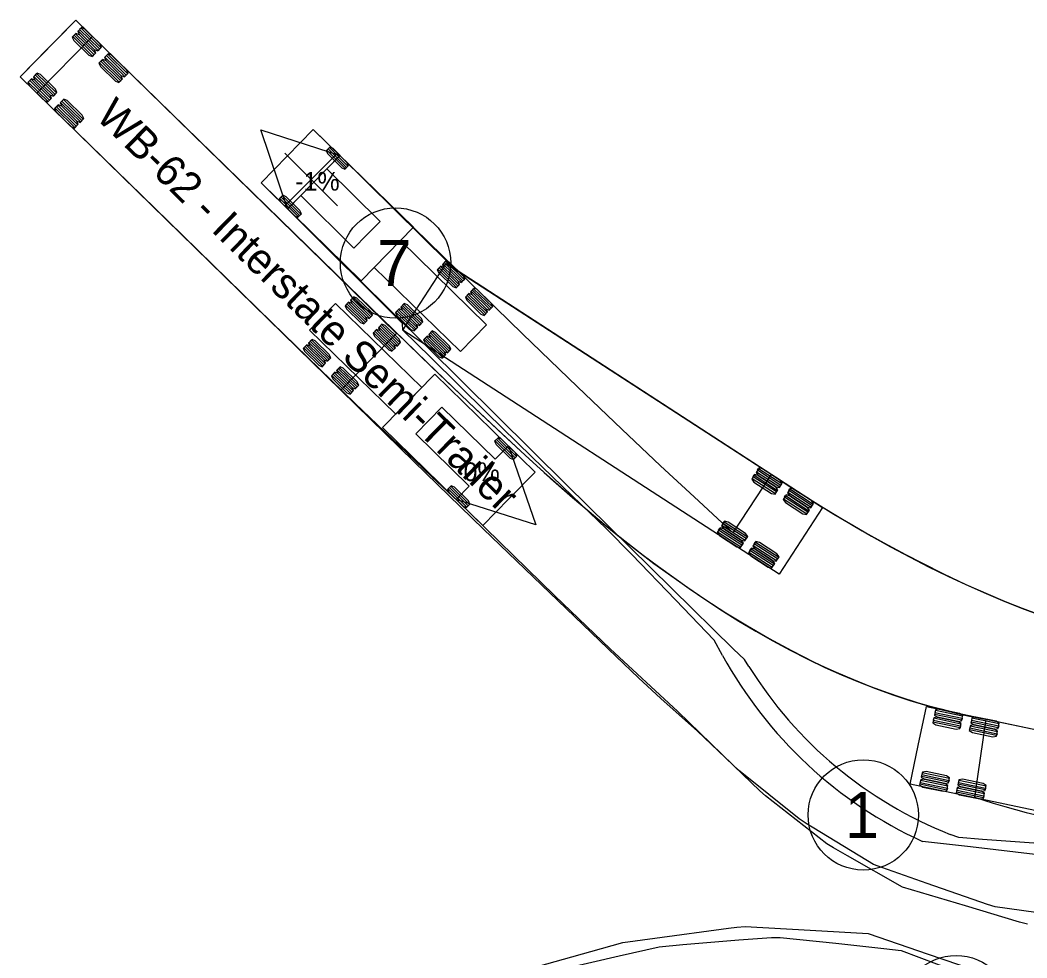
# Model space of a CAD drawing. Extents: x 1475900 to 1484331, y 375914 to 383395.
# Drawn here: x 1478966.1 to 1479073.9, y 379974.6 to 380075 of the extents above; entities that cross this region are included whole.
import ezdxf

# ---------------------------------------------------------------- set-up
doc = ezdxf.new("R2010")
doc.units = 0
doc.layers.add('0 (Construction)', color=7, linetype='Continuous')
doc.layers.add('Default', color=7, linetype='Continuous')

# ---------------------------------------------------------------- blocks, each defined once
blk = doc.blocks.new('ATRPTH')
at = {"layer": '0 (Construction)'}
blk.add_lwpolyline([(375813.922, 96513.365), (375814.277, 96513.729), (375815.731, 96512.309), (375816.086, 96512.672), (375816.829, 96510.525), (375814.666, 96511.219), (375815.021, 96511.582), (375813.567, 96513.002), (375813.922, 96513.365)], dxfattribs=at)
blk.add_circle((375825.735, 96502.636), 1.5, dxfattribs=at)
at = {"layer": 'Default'}
for points in [[(375804.321, 96524.255), (375811.738, 96517.015), (375813.875, 96514.943), (375815.01, 96513.855), (375815.898, 96513.017), (375816.541, 96512.422), (375817.056, 96511.954), (375817.581, 96511.49), (375818.11, 96511.033), (375818.515, 96510.692), (375818.921, 96510.358), (375819.336, 96510.029), (375819.752, 96509.704), (375820.165, 96509.395), (375820.58, 96509.093), (375821.005, 96508.796), (375821.429, 96508.508), (375821.999, 96508.136), (375822.586, 96507.777), (375823.179, 96507.434), (375823.781, 96507.109), (375824.081, 96506.954), (375824.384, 96506.805), (375824.689, 96506.659), (375824.999, 96506.519), (375825.467, 96506.316), (375825.936, 96506.128), (375826.408, 96505.954), (375826.725, 96505.847), (375827.202, 96505.695), (375827.522, 96505.603), (375827.843, 96505.518), (375828.326, 96505.399), (375828.811, 96505.296), (375838.843, 96503.191)], [(375830.197, 96499.665), (375829.983, 96499.716), (375828.516, 96500.162), (375826.802, 96500.673), (375825.304, 96501.525), (375824.926, 96501.739), (375824.744, 96501.854), (375823.076, 96503.156), (375822.92, 96503.295), (375821.984, 96504.199), (375821.231, 96504.913), (375820.234, 96505.805), (375819.622, 96506.37), (375819.018, 96506.943), (375815.408, 96510.407), (375813.526, 96512.244), (375802.812, 96522.711), (375804.321, 96524.255)], [(375811.533, 96514.191), (375802.812, 96522.711), (375803.566, 96523.483), (375804.321, 96524.255), (375813.041, 96515.735), (375812.287, 96514.963), (375811.533, 96514.191), (375811.533, 96514.191)], [(375805.007, 96523.509), (375804.467, 96524.037), (375804.429, 96523.998), (375804.97, 96523.47), (375804.932, 96523.432), (375804.391, 96523.96), (375804.379, 96523.947), (375804.421, 96523.855), (375804.827, 96523.459), (375804.919, 96523.419), (375805.02, 96523.522), (375804.977, 96523.613), (375804.572, 96524.01), (375804.479, 96524.05), (375804.379, 96523.947)], [(375804.775, 96523.811), (375811.766, 96516.988), (375814, 96514.823), (375815.189, 96513.684), (375815.931, 96512.984), (375816.66, 96512.311), (375817.241, 96511.787), (375817.831, 96511.269), (375818.279, 96510.886), (375818.721, 96510.517), (375819.156, 96510.165), (375819.597, 96509.818), (375820.045, 96509.478), (375820.501, 96509.145), (375820.963, 96508.819), (375821.43, 96508.501), (375821.904, 96508.192), (375822.353, 96507.911), (375822.81, 96507.638), (375823.274, 96507.374), (375823.745, 96507.12), (375824.224, 96506.876), (375824.692, 96506.65), (375825.143, 96506.447), (375825.601, 96506.253), (375826.066, 96506.071), (375826.538, 96505.901), (375826.999, 96505.749), (375827.31, 96505.655), (375827.782, 96505.526), (375828.259, 96505.407), (375828.581, 96505.336), (375828.906, 96505.271), (375829.07, 96505.241), (375828.755, 96503.117), (375829.266, 96502.959), (375829.587, 96502.865), (375830.16, 96502.707), (375830.519, 96502.625)], [(375830.431, 96499.985), (375829.325, 96500.141), (375829.111, 96500.202), (375827.476, 96500.77), (375826.238, 96501.208), (375826.012, 96501.292), (375824.178, 96502.406), (375823.994, 96502.53), (375822.344, 96503.856), (375822.186, 96503.999), (375820.694, 96505.446), (375818.853, 96507.152), (375817.348, 96508.598), (375814.709, 96511.172), (375814.003, 96511.834), (375813.112, 96512.681), (375811.919, 96513.831), (375809.658, 96516.026), (375806.842, 96518.773), (375803.266, 96522.267), (375804.775, 96523.811)], [(375804.856, 96523.354), (375804.316, 96523.882), (375804.278, 96523.844), (375804.819, 96523.316), (375804.781, 96523.277), (375804.24, 96523.805), (375804.228, 96523.792), (375804.27, 96523.701), (375804.676, 96523.305), (375804.768, 96523.264), (375804.869, 96523.367), (375804.827, 96523.459), (375804.421, 96523.855), (375804.329, 96523.895), (375804.228, 96523.792)], [(375805.734, 96522.799), (375805.194, 96523.327), (375805.156, 96523.288), (375805.696, 96522.76), (375805.659, 96522.722), (375805.118, 96523.25), (375805.106, 96523.237), (375805.148, 96523.145), (375805.553, 96522.749), (375805.646, 96522.709), (375805.747, 96522.812), (375805.704, 96522.903), (375805.299, 96523.3), (375805.206, 96523.34), (375805.106, 96523.237)], [(375805.583, 96522.644), (375805.043, 96523.172), (375805.005, 96523.134), (375805.545, 96522.606), (375805.508, 96522.567), (375804.967, 96523.095), (375804.955, 96523.082), (375804.997, 96522.991), (375805.402, 96522.595), (375805.495, 96522.554), (375805.596, 96522.657), (375805.553, 96522.749), (375805.148, 96523.145), (375805.055, 96523.185), (375804.955, 96523.082)], [(375803.649, 96522.119), (375803.109, 96522.647), (375803.071, 96522.608), (375803.612, 96522.08), (375803.574, 96522.042), (375803.033, 96522.57), (375803.021, 96522.557), (375803.063, 96522.465), (375803.469, 96522.069), (375803.561, 96522.029), (375803.662, 96522.132), (375803.62, 96522.224), (375803.214, 96522.62), (375803.121, 96522.66), (375803.021, 96522.557)], [(375803.8, 96522.273), (375803.26, 96522.801), (375803.222, 96522.763), (375803.763, 96522.235), (375803.725, 96522.196), (375803.184, 96522.724), (375803.172, 96522.711), (375803.214, 96522.62), (375803.62, 96522.224), (375803.712, 96522.183), (375803.813, 96522.286), (375803.77, 96522.378), (375803.365, 96522.774), (375803.272, 96522.814), (375803.172, 96522.711)], [(375804.376, 96521.409), (375803.836, 96521.937), (375803.798, 96521.898), (375804.338, 96521.37), (375804.301, 96521.332), (375803.76, 96521.86), (375803.748, 96521.847), (375803.79, 96521.755), (375804.195, 96521.359), (375804.288, 96521.319), (375804.389, 96521.422), (375804.346, 96521.514), (375803.941, 96521.91), (375803.848, 96521.95), (375803.748, 96521.847)], [(375804.527, 96521.563), (375803.987, 96522.091), (375803.949, 96522.053), (375804.489, 96521.525), (375804.452, 96521.486), (375803.911, 96522.014), (375803.899, 96522.001), (375803.941, 96521.91), (375804.346, 96521.514), (375804.439, 96521.473), (375804.54, 96521.576), (375804.497, 96521.668), (375804.092, 96522.064), (375803.999, 96522.104), (375803.899, 96522.001)], [(375812.38, 96516.221), (375811.871, 96516.718), (375811.836, 96516.682), (375812.345, 96516.185), (375812.309, 96516.149), (375811.8, 96516.646), (375811.789, 96516.634), (375811.828, 96516.547), (375812.21, 96516.175), (375812.297, 96516.137), (375812.392, 96516.234), (375812.352, 96516.32), (375811.97, 96516.693), (375811.883, 96516.731), (375811.789, 96516.634)], [(375813.732, 96514.261), (375811.388, 96516.551), (375810.678, 96515.824), (375813.022, 96513.535), (375813.732, 96514.261)], [(375812.238, 96516.076), (375811.729, 96516.573), (375811.694, 96516.537), (375812.203, 96516.04), (375812.167, 96516.003), (375811.658, 96516.5), (375811.647, 96516.488), (375811.686, 96516.402), (375812.068, 96516.029), (375812.155, 96515.991), (375812.25, 96516.088), (375812.21, 96516.175), (375811.828, 96516.547), (375811.741, 96516.585), (375811.647, 96516.488)], [(375813.001, 96515.331), (375812.492, 96515.828), (375812.457, 96515.791), (375812.966, 96515.294), (375812.93, 96515.258), (375812.421, 96515.755), (375812.41, 96515.743), (375812.449, 96515.656), (375812.831, 96515.284), (375812.918, 96515.246), (375813.013, 96515.343), (375812.973, 96515.429), (375812.591, 96515.802), (375812.504, 96515.84), (375812.41, 96515.743)], [(375813.143, 96515.476), (375812.634, 96515.973), (375812.599, 96515.937), (375813.108, 96515.44), (375813.072, 96515.403), (375812.563, 96515.9), (375812.552, 96515.888), (375812.591, 96515.802), (375812.973, 96515.429), (375813.06, 96515.391), (375813.155, 96515.488), (375813.115, 96515.574), (375812.733, 96515.947), (375812.646, 96515.985), (375812.552, 96515.888)], [(375811.244, 96515.059), (375810.735, 96515.556), (375810.7, 96515.519), (375811.209, 96515.022), (375811.173, 96514.986), (375810.664, 96515.483), (375810.652, 96515.471), (375810.692, 96515.385), (375811.074, 96515.012), (375811.161, 96514.974), (375811.256, 96515.071), (375811.216, 96515.157), (375810.834, 96515.53), (375810.747, 96515.568), (375810.652, 96515.471)], [(375811.102, 96514.913), (375810.593, 96515.41), (375810.558, 96515.374), (375811.067, 96514.877), (375811.031, 96514.841), (375810.522, 96515.338), (375810.51, 96515.326), (375810.55, 96515.239), (375810.932, 96514.866), (375811.019, 96514.828), (375811.114, 96514.925), (375811.074, 96515.012), (375810.692, 96515.385), (375810.605, 96515.422), (375810.51, 96515.326)], [(375812.007, 96514.313), (375811.498, 96514.81), (375811.463, 96514.774), (375811.972, 96514.277), (375811.936, 96514.24), (375811.427, 96514.737), (375811.416, 96514.725), (375811.455, 96514.639), (375811.837, 96514.266), (375811.924, 96514.228), (375812.019, 96514.325), (375811.979, 96514.412), (375811.597, 96514.784), (375811.51, 96514.822), (375811.416, 96514.725)], [(375811.865, 96514.168), (375811.356, 96514.665), (375811.321, 96514.628), (375811.83, 96514.131), (375811.794, 96514.095), (375811.285, 96514.592), (375811.274, 96514.58), (375811.313, 96514.494), (375811.695, 96514.121), (375811.782, 96514.083), (375811.877, 96514.18), (375811.837, 96514.266), (375811.455, 96514.639), (375811.368, 96514.677), (375811.274, 96514.58)], [(375815.392, 96510.509), (375812.667, 96513.171), (375814.087, 96514.625), (375816.812, 96511.962), (375816.102, 96511.235), (375815.392, 96510.509), (375815.392, 96510.509)], [(375816.304, 96512.387), (375815.796, 96512.884), (375815.76, 96512.848), (375816.269, 96512.351), (375816.233, 96512.315), (375815.725, 96512.812), (375815.713, 96512.8), (375815.753, 96512.713), (375816.134, 96512.34), (375816.222, 96512.303), (375816.316, 96512.399), (375816.276, 96512.486), (375815.895, 96512.859), (375815.808, 96512.896), (375815.713, 96512.8)], [(375815.026, 96511.079), (375814.518, 96511.576), (375814.482, 96511.54), (375814.991, 96511.043), (375814.955, 96511.007), (375814.447, 96511.504), (375814.435, 96511.491), (375814.475, 96511.405), (375814.856, 96511.032), (375814.944, 96510.994), (375815.038, 96511.091), (375814.998, 96511.178), (375814.617, 96511.55), (375814.53, 96511.588), (375814.435, 96511.491)], [(375838.939, 96500.954), (375827.009, 96503.469), (375827.231, 96504.525), (375827.454, 96505.582), (375839.384, 96503.067), (375839.161, 96502.011), (375838.939, 96500.954), (375838.939, 96500.954)], [(375828.434, 96505.32), (375827.695, 96505.476), (375827.683, 96505.423), (375828.423, 96505.267), (375828.412, 96505.214), (375827.672, 96505.37), (375827.669, 96505.352), (375827.754, 96505.298), (375828.308, 96505.181), (375828.408, 96505.197), (375828.438, 96505.337), (375828.353, 96505.392), (375827.798, 96505.509), (375827.698, 96505.493), (375827.669, 96505.352)], [(375828.389, 96505.109), (375827.65, 96505.264), (375827.639, 96505.212), (375828.378, 96505.056), (375828.367, 96505.003), (375827.628, 96505.159), (375827.624, 96505.141), (375827.709, 96505.086), (375828.264, 96504.97), (375828.363, 96504.985), (375828.393, 96505.126), (375828.308, 96505.181), (375827.754, 96505.298), (375827.654, 96505.282), (375827.624, 96505.141)], [(375829.428, 96505.11), (375828.689, 96505.266), (375828.678, 96505.213), (375829.417, 96505.057), (375829.406, 96505.005), (375828.666, 96505.16), (375828.663, 96505.143), (375828.748, 96505.088), (375829.302, 96504.971), (375829.402, 96504.987), (375829.432, 96505.128), (375829.347, 96505.183), (375828.792, 96505.299), (375828.692, 96505.284), (375828.663, 96505.143)], [(375829.384, 96504.899), (375828.644, 96505.055), (375828.633, 96505.002), (375829.372, 96504.846), (375829.361, 96504.793), (375828.622, 96504.949), (375828.618, 96504.932), (375828.703, 96504.877), (375829.258, 96504.76), (375829.358, 96504.776), (375829.387, 96504.917), (375829.302, 96504.971), (375828.748, 96505.088), (375828.648, 96505.072), (375828.618, 96504.932)], [(375828.078, 96503.63), (375827.338, 96503.786), (375827.327, 96503.733), (375828.067, 96503.577), (375828.055, 96503.524), (375827.316, 96503.68), (375827.312, 96503.662), (375827.397, 96503.608), (375827.952, 96503.491), (375828.052, 96503.506), (375828.081, 96503.647), (375827.996, 96503.702), (375827.442, 96503.819), (375827.342, 96503.803), (375827.312, 96503.662)], [(375828.033, 96503.418), (375827.294, 96503.574), (375827.283, 96503.522), (375828.022, 96503.366), (375828.011, 96503.313), (375827.272, 96503.469), (375827.268, 96503.451), (375827.353, 96503.396), (375827.907, 96503.28), (375828.007, 96503.295), (375828.037, 96503.436), (375827.952, 96503.491), (375827.397, 96503.608), (375827.297, 96503.592), (375827.268, 96503.451)], [(375829.072, 96503.42), (375828.332, 96503.576), (375828.321, 96503.523), (375829.061, 96503.367), (375829.05, 96503.315), (375828.31, 96503.47), (375828.306, 96503.453), (375828.391, 96503.398), (375828.946, 96503.281), (375829.046, 96503.297), (375829.076, 96503.438), (375828.991, 96503.492), (375828.436, 96503.609), (375828.336, 96503.594), (375828.306, 96503.453)], [(375829.027, 96503.209), (375828.288, 96503.365), (375828.277, 96503.312), (375829.016, 96503.156), (375829.005, 96503.103), (375828.266, 96503.259), (375828.262, 96503.242), (375828.347, 96503.187), (375828.902, 96503.07), (375829.001, 96503.086), (375829.031, 96503.227), (375828.946, 96503.281), (375828.391, 96503.398), (375828.292, 96503.382), (375828.262, 96503.242)]]:
    blk.add_lwpolyline(points, dxfattribs=at)
at = {"layer": '0 (Construction)'}
for s, height, p in [('0%', 0.508, (375814.868, 96511.717)), ('1', 1.25, (375825.235, 96502.011))]:
    blk.add_text(s, height=height, dxfattribs=at).set_placement(p)
at = {"layer": 'Default'}
blk.add_text('WB-62 - Interstate Semi-Trailer', height=0.83333, rotation=315.6667, dxfattribs=at).set_placement((375804.834, 96521.603))
blk = doc.blocks.new('ATRPTH_2')
at = {"layer": '0 (Construction)'}
blk.add_circle((375828.26, 96497.315), 1.5, dxfattribs=at)
at = {"layer": 'Default'}
for points in [[(375816.618, 96498.442), (375818.325, 96498.922), (375819.195, 96499.17), (375820.069, 96499.286), (375822.072, 96499.555), (375822.299, 96499.586), (375822.524, 96499.602), (375824.289, 96499.498), (375825.87, 96499.41), (375827.498, 96498.848), (375829.15, 96498.284)], [(375817.612, 96498.462), (375819.096, 96498.808), (375820.182, 96499.052), (375820.831, 96499.11), (375822.356, 96499.237), (375823.243, 96499.304), (375823.475, 96499.307), (375824.988, 96499.151), (375826.298, 96499.007), (375826.762, 96498.95), (375829.168, 96498.042)]]:
    blk.add_lwpolyline(points, dxfattribs=at)
blk = doc.blocks.new('ATRPTH_7')
at = {"layer": '0 (Construction)'}
for p, q in [((375810.004, 96519.199), (375811.443, 96520.638)), ((375811.443, 96519.199), (375810.004, 96520.638))]:
    blk.add_line(p, q, dxfattribs=at)
blk.add_lwpolyline([(375812.241, 96518.417), (375811.884, 96518.056), (375810.439, 96519.485), (375810.082, 96519.124), (375809.353, 96521.275), (375811.512, 96520.568), (375811.154, 96520.207), (375812.598, 96518.778), (375812.241, 96518.417)], dxfattribs=at)
blk.add_circle((375813.018, 96517.648), 1.5, dxfattribs=at)
at = {"layer": 'Default'}
for points in [[(375821.907, 96506.975), (375821.683, 96507.388), (375820.633, 96508.487), (375819.44, 96509.72), (375818.758, 96510.419), (375817.816, 96511.317), (375816.73, 96512.369), (375815.5, 96513.571), (375813.976, 96515.074), (375813.219, 96515.825), (375813.211, 96516.002), (375810.249, 96518.948), (375809.36, 96519.83), (375810.78, 96521.283), (375814.693, 96517.454), (375824.128, 96511.323), (375824.556, 96511.055), (375825.129, 96510.706), (375825.709, 96510.367), (375826.295, 96510.036), (375826.88, 96509.719), (375827.323, 96509.489), (375827.919, 96509.193), (375828.523, 96508.907), (375829.132, 96508.638), (375829.593, 96508.444), (375830.054, 96508.261), (375830.516, 96508.088)], [(375810.78, 96521.283), (375813.505, 96518.62), (375812.085, 96517.167), (375809.36, 96519.83), (375810.07, 96520.556), (375810.78, 96521.283), (375810.78, 96521.283)], [(375811.147, 96520.714), (375811.653, 96520.214), (375811.689, 96520.25), (375811.183, 96520.75), (375811.219, 96520.786), (375811.724, 96520.286), (375811.736, 96520.298), (375811.697, 96520.385), (375811.318, 96520.76), (375811.231, 96520.798), (375811.136, 96520.702), (375811.175, 96520.615), (375811.554, 96520.24), (375811.641, 96520.202), (375811.736, 96520.298)], [(375822.625, 96506.677), (375822.504, 96506.864), (375822.21, 96507.147), (375820.53, 96508.796), (375817.67, 96511.618), (375810.086, 96519.12), (375811.507, 96520.572), (375814.464, 96517.647), (375814.668, 96517.484), (375816.474, 96515.722), (375817.968, 96514.277), (375819.169, 96513.129), (375820.224, 96512.131), (375821.133, 96511.284), (375821.895, 96510.585), (375822.201, 96510.308), (375823.237, 96511.898), (375823.905, 96511.461), (375824.427, 96511.132), (375824.936, 96510.819), (375825.447, 96510.515), (375825.961, 96510.219), (375826.476, 96509.932), (375826.993, 96509.655), (375827.512, 96509.389), (375828.032, 96509.133), (375828.523, 96508.904), (375829.009, 96508.686), (375829.523, 96508.468), (375830.037, 96508.263), (375830.55, 96508.071)], [(375809.869, 96519.406), (375810.375, 96518.906), (375810.411, 96518.942), (375809.905, 96519.442), (375809.941, 96519.478), (375810.446, 96518.978), (375810.458, 96518.99), (375810.419, 96519.077), (375810.04, 96519.452), (375809.953, 96519.49), (375809.857, 96519.394), (375809.897, 96519.307), (375810.276, 96518.932), (375810.363, 96518.894), (375810.458, 96518.99)], [(375812.44, 96517.53), (375814.784, 96515.24), (375815.494, 96515.967), (375813.15, 96518.257), (375812.44, 96517.53)], [(375814.394, 96517.636), (375824.622, 96510.999), (375824.034, 96510.093), (375823.446, 96509.188), (375813.219, 96515.825), (375813.807, 96516.73), (375814.394, 96517.636), (375814.394, 96517.636)], [(375814.165, 96517.478), (375814.674, 96516.981), (375814.709, 96517.017), (375814.201, 96517.514), (375814.236, 96517.551), (375814.745, 96517.054), (375814.756, 96517.066), (375814.717, 96517.152), (375814.335, 96517.525), (375814.248, 96517.563), (375814.153, 96517.466), (375814.193, 96517.38), (375814.575, 96517.007), (375814.662, 96516.969), (375814.756, 96517.066)], [(375814.307, 96517.623), (375814.816, 96517.126), (375814.851, 96517.163), (375814.343, 96517.66), (375814.378, 96517.696), (375814.887, 96517.199), (375814.899, 96517.211), (375814.859, 96517.297), (375814.477, 96517.67), (375814.39, 96517.708), (375814.295, 96517.611), (375814.335, 96517.525), (375814.717, 96517.152), (375814.804, 96517.114), (375814.899, 96517.211)], [(375815.07, 96516.878), (375815.579, 96516.381), (375815.614, 96516.417), (375815.106, 96516.914), (375815.141, 96516.95), (375815.65, 96516.453), (375815.662, 96516.465), (375815.622, 96516.552), (375815.24, 96516.925), (375815.153, 96516.963), (375815.058, 96516.866), (375815.098, 96516.779), (375815.48, 96516.406), (375815.567, 96516.369), (375815.662, 96516.465)], [(375814.928, 96516.732), (375815.437, 96516.235), (375815.472, 96516.272), (375814.963, 96516.769), (375814.999, 96516.805), (375815.508, 96516.308), (375815.519, 96516.32), (375815.48, 96516.406), (375815.098, 96516.779), (375815.011, 96516.817), (375814.916, 96516.72), (375814.956, 96516.634), (375815.338, 96516.261), (375815.425, 96516.223), (375815.519, 96516.32)], [(375813.029, 96516.315), (375813.538, 96515.818), (375813.573, 96515.855), (375813.064, 96516.352), (375813.1, 96516.388), (375813.609, 96515.891), (375813.62, 96515.903), (375813.58, 96515.989), (375813.199, 96516.362), (375813.112, 96516.4), (375813.017, 96516.303), (375813.057, 96516.217), (375813.438, 96515.844), (375813.526, 96515.806), (375813.62, 96515.903)], [(375813.171, 96516.461), (375813.68, 96515.964), (375813.715, 96516), (375813.206, 96516.497), (375813.242, 96516.533), (375813.751, 96516.036), (375813.762, 96516.048), (375813.722, 96516.135), (375813.341, 96516.508), (375813.254, 96516.545), (375813.159, 96516.449), (375813.199, 96516.362), (375813.58, 96515.989), (375813.668, 96515.952), (375813.762, 96516.048)], [(375813.792, 96515.57), (375814.3, 96515.073), (375814.336, 96515.109), (375813.827, 96515.606), (375813.863, 96515.642), (375814.371, 96515.145), (375814.383, 96515.158), (375814.343, 96515.244), (375813.962, 96515.617), (375813.875, 96515.655), (375813.78, 96515.558), (375813.82, 96515.471), (375814.201, 96515.099), (375814.289, 96515.061), (375814.383, 96515.158)], [(375813.934, 96515.715), (375814.443, 96515.218), (375814.478, 96515.254), (375813.969, 96515.751), (375814.005, 96515.788), (375814.514, 96515.291), (375814.525, 96515.303), (375814.485, 96515.389), (375814.104, 96515.762), (375814.017, 96515.8), (375813.922, 96515.703), (375813.962, 96515.617), (375814.343, 96515.244), (375814.431, 96515.206), (375814.525, 96515.303)], [(375862.173, 96515.694), (375849.779, 96509.345), (375848.49, 96508.686), (375840.022, 96504.346), (375839.655, 96504.169), (375839.282, 96503.998), (375838.57, 96503.68), (375835.624, 96502.13), (375835.193, 96502.041), (375833.695, 96501.737), (375832.219, 96501.428), (375832.009, 96501.383), (375831.782, 96501.393), (375828.648, 96501.769), (375827.343, 96501.918)], [(375861.607, 96515.404), (375848.11, 96508.5), (375847.026, 96507.963), (375846.321, 96507.623), (375845.593, 96507.278), (375842.137, 96505.505), (375841.397, 96505.123), (375841.023, 96504.921), (375840.644, 96504.728), (375840.259, 96504.539), (375840.029, 96504.431), (375839.475, 96504.144), (375836.527, 96502.598), (375836.295, 96502.535), (375834.615, 96502.128), (375832.951, 96501.731), (375832.707, 96501.725), (375831.814, 96501.776), (375830.498, 96501.862), (375828.98, 96501.971), (375828.335, 96502.02), (375828.096, 96502.107)], [(375822.831, 96511.967), (375823.465, 96511.556), (375823.495, 96511.601), (375822.861, 96512.013), (375822.89, 96512.058), (375823.524, 96511.647), (375823.534, 96511.662), (375823.474, 96511.743), (375822.999, 96512.052), (375822.9, 96512.073), (375822.822, 96511.952), (375822.881, 96511.871), (375823.357, 96511.562), (375823.456, 96511.541), (375823.534, 96511.662)], [(375822.714, 96511.786), (375823.348, 96511.375), (375823.377, 96511.42), (375822.743, 96511.832), (375822.773, 96511.877), (375823.407, 96511.465), (375823.416, 96511.481), (375823.357, 96511.562), (375822.881, 96511.871), (375822.782, 96511.892), (375822.704, 96511.771), (375822.764, 96511.69), (375823.239, 96511.381), (375823.338, 96511.36), (375823.416, 96511.481)], [(375823.684, 96511.414), (375824.318, 96511.003), (375824.347, 96511.048), (375823.713, 96511.46), (375823.742, 96511.505), (375824.376, 96511.093), (375824.386, 96511.109), (375824.326, 96511.19), (375823.851, 96511.499), (375823.752, 96511.52), (375823.674, 96511.399), (375823.734, 96511.318), (375824.209, 96511.009), (375824.308, 96510.988), (375824.386, 96511.109)], [(375823.566, 96511.233), (375824.2, 96510.822), (375824.229, 96510.867), (375823.596, 96511.278), (375823.625, 96511.324), (375824.259, 96510.912), (375824.269, 96510.927), (375824.209, 96511.009), (375823.734, 96511.318), (375823.635, 96511.339), (375823.556, 96511.218), (375823.616, 96511.136), (375824.091, 96510.828), (375824.19, 96510.807), (375824.269, 96510.927)], [(375821.891, 96510.518), (375822.525, 96510.107), (375822.554, 96510.152), (375821.921, 96510.564), (375821.95, 96510.609), (375822.584, 96510.198), (375822.594, 96510.213), (375822.534, 96510.294), (375822.059, 96510.603), (375821.96, 96510.624), (375821.881, 96510.503), (375821.941, 96510.422), (375822.416, 96510.113), (375822.515, 96510.092), (375822.594, 96510.213)], [(375821.774, 96510.337), (375822.408, 96509.926), (375822.437, 96509.971), (375821.803, 96510.383), (375821.832, 96510.428), (375822.466, 96510.017), (375822.476, 96510.032), (375822.416, 96510.113), (375821.941, 96510.422), (375821.842, 96510.443), (375821.764, 96510.322), (375821.824, 96510.241), (375822.299, 96509.932), (375822.398, 96509.911), (375822.476, 96510.032)], [(375822.743, 96509.965), (375823.377, 96509.554), (375823.407, 96509.599), (375822.773, 96510.011), (375822.802, 96510.056), (375823.436, 96509.645), (375823.446, 96509.66), (375823.386, 96509.741), (375822.911, 96510.05), (375822.812, 96510.071), (375822.734, 96509.95), (375822.793, 96509.869), (375823.269, 96509.56), (375823.368, 96509.539), (375823.446, 96509.66)], [(375822.626, 96509.784), (375823.26, 96509.373), (375823.289, 96509.418), (375822.655, 96509.83), (375822.685, 96509.875), (375823.319, 96509.464), (375823.328, 96509.479), (375823.269, 96509.56), (375822.793, 96509.869), (375822.694, 96509.89), (375822.616, 96509.769), (375822.676, 96509.688), (375823.151, 96509.379), (375823.25, 96509.358), (375823.328, 96509.479)]]:
    blk.add_lwpolyline(points, dxfattribs=at)
for radius, start, end in [(11.798, 208.7216, 245.4014), (11.328, 211.7894, 248.4692)]:
    blk.add_arc((375832.254, 96512.645), radius, start, end, dxfattribs=at)
at = {"layer": '0 (Construction)'}
for s, height, p in [('-1%', 0.508, (375810.289, 96519.617)), ('7', 1.25, (375812.518, 96517.023))]:
    blk.add_text(s, height=height, dxfattribs=at).set_placement(p)

msp = doc.modelspace()

# ---------------------------------------------------------------- block references
at = {"layer": 'Default', "xscale": 3.937007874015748, "yscale": 3.937007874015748}
for name in ['ATRPTH', 'ATRPTH_7', 'ATRPTH_2']:
    msp.add_blockref(name, (-572.52, 58.24), dxfattribs=at)

doc.saveas('drawing.dxf')
